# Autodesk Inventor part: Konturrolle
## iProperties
Created: 2010-05
Part Number: Konturrolle
Material: Standard
Document SubType Name: Blech
Designer: Udo.Huebner
Density: 1 g/cm^3
Flat Pattern Width: 90 cm
Flat Pattern Length: 217.398 cm
Flat Pattern Area: 19565.8 cm^2
Sheet Metal Rule: Standard_mm
Author: Udo.Huebner
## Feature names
1. Extrusion Differenz Rechteck
2. Rechteckige Anordnung Rechteck [Rectangular Pattern]
